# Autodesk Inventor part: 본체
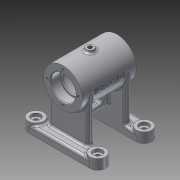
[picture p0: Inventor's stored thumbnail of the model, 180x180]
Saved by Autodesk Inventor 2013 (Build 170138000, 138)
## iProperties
Created: 2015-11
Part Number: 본체
Material: 알루미늄 6061
Document SubType Name: Modeling
Designer: cad10
Density: 2.40731 g/cm^3
Mass: 318.269 g
Surface Area: 455.809 cm^2
Volume: 132.209 cm^3
Author: cad10
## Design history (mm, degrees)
sketch "스케치1"
  geometry: L1 (-40, -20)-(40, -20); L2 (50, -30)-(50, -30); L3 (40, -40)-(-40, -40); L4 (-50, -30)-(-50, -30); L5 (-40, 40)-(40, 40); L6 (50, 30)-(50, 30); L7 (40, 20)-(-40, 20); L8 (-50, 30)-(-50, 30); A1 r 10 centre (-40, 30) between (-40, 40) and (-50, 30); A2 r 10 centre (-40, 30) between (-50, 30) and (-40, 20); A3 r 10 centre (40, 30) between (40, 20) and (50, 30); A4 r 10 centre (40, 30) between (50, 30) and (40, 40); A5 r 10 centre (40, -30) between (50, -30) and (40, -20); A6 r 10 centre (40, -30) between (40, -40) and (50, -30); A7 r 10 centre (-40, -30) between (-50, -30) and (-40, -40); A8 r 10 centre (-40, -30) between (-40, -20) and (-50, -30); 3 further points
  constraints: 16 end point, 16 point on circle, 16 tangent, 8 centre point, 7 equal radius, 4 parallel, 2 horizontal, 2 midpoint, 2 perpendicular, 2 vertical alignment
  dimensions: "d0" = 100 distance between parallel lines of L8 L6; "d2" = 20 distance between parallel lines of L5 L7; "d3" = 20 distance between parallel lines of L3 L1; "d4" = 100 distance between parallel lines of L4 L2; "d5" = 80 distance between parallel lines of L5 L3; "d6" = 40 distance from line of L5 point (0, 0); "d7" = 10 radius of A1
extrude "돌출1" new body sketch "스케치1" distance "d8" = 10; taper "d9" = 0 deg
sketch "스케치2"
  geometry: C1 r 10 at (-40, -30); A1 r 10 centre (40, -30) between (40, -40) and (40, -20) reference; A2 r 10 centre (-40, -30) between (-40, -20) and (-40, -40) reference; 2 further points
  constraints: 2 coincident, 1 centre point, 1 concentric, 1 vertical alignment, 2 other
extrude "돌출2" join sketch "스케치2" distance "d10" = 3; taper "d11" = 0 deg
sketch "스케치3"
  geometry: A1 r 10 centre (-40, 30) between (-40, 40) and (-40, 20) reference; A2 r 10 centre (40, 30) between (40, 20) and (40, 40) reference; 3 further points
  constraints: 2 coincident, 2 vertical alignment, 4 other
extrude "돌출3" join sketch "스케치3" distance "d12" = 3; taper "d13" = 0 deg
node "작업 평면2"
sketch "스케치5"
  geometry: L1 (-40, 0)-(40, 0) reference; C1 r 25 at (0, 68); 2 further points
  constraints: 1 centre point, 1 midpoint, 1 vertical alignment
  dimensions: "d16" = 50 diameter of C1; "d18" = 68 distance from line of C1.centre L1
extrude "돌출4" join sketch "스케치5" stored distance "d19" = 70; taper "d20" = 0 deg
node "작업 평면3"
sketch "스케치6"
  geometry: L1 (-35, 93)-(-35, 43) reference; L2 (35, 43)-(35, 93) reference; L3 (-35, 84)-(-23, 84); L4 (-23, 84)-(-23, 82); L5 (-23, 82)-(-21, 82); L6 (-21, 82)-(-21, 89); L7 (-21, 89)-(21, 89); L8 (21, 89)-(21, 82); L9 (21, 82)-(23, 82); L10 (23, 82)-(23, 84); L11 (23, 84)-(35, 84); L12 (-35, 68)-(35, 68); 1 further point
  constraints: 20 end point, 6 parallel, 3 perpendicular, 2 midpoint, 2 point on line
  dimensions: "d22" = 32 diameter of L3 L12; "d24" = 28 diameter of L5 L12; "d25" = 42 diameter of L7 L12; "d26" = 28 diameter of L9 L12; "d27" = 32 diameter of L11 L12; "d28" = 12 distance between parallel lines of L2 L10; "d29" = 12 distance between parallel lines of L1 L4; "d30" = 42 distance between parallel lines of L8 L6; "d31" = 2 distance between parallel lines of L4 L6
revolve "회전1" sketch "스케치6" stored, may be unused: angle "d32" = 90 deg
sketch "스케치7"
  geometry: L1 (40, -20)-(-40, -20) reference; L2 (-25, -20)-(25, -20); L3 (25, -20)-(25, -28); L4 (25, -28)-(-25, -28); L5 (-25, -28)-(-25, -20); 3 further points
  constraints: 8 end point, 2 midpoint, 2 parallel, 2 vertical alignment, 1 horizontal, 1 perpendicular, 1 point on line
  dimensions: "d33" = 50 distance between parallel lines of L3 L5; "d35" = 8 distance between parallel lines of L1 L4
extrude "돌출5" join sketch "스케치7" stored distance "d38" = 0; taper "d39" = 0 deg
sketch "스케치8"
  geometry: L1 (-40, 20)-(40, 20) reference; L2 (-25, 20)-(25, 20); L3 (25, 20)-(25, 28); L4 (25, 28)-(-25, 28); L5 (-25, 28)-(-25, 20); 3 further points
  constraints: 8 end point, 2 midpoint, 2 parallel, 2 vertical alignment, 1 horizontal, 1 perpendicular, 1 point on line
  dimensions: "d40" = 8 distance between parallel lines of L4 L2; "d42" = 50 distance between parallel lines of L5 L3
extrude "돌출6" join sketch "스케치8" stored distance "d43" = 70; taper "d44" = 0 deg
node "작업 평면4"
sketch "스케치9"
  geometry: C1 r 5 at (0, 0); 1 further point
  constraints: 1 centre point, 1 coincident
  dimensions: "d46" = 10 diameter of C1
extrude "돌출7" join sketch "스케치9" stored distance "d48" = 70; taper "d49" = 0 deg
sketch "스케치10"
  geometry: C1 r 16 at (0, 0) reference; 2 further points
  constraints: 1 vertical alignment
  dimensions: "d50" = 20 distance of point (0, 20) C1.centre
hole "구멍1" sketch "스케치10" at (0, 20) diameter "d51" = 3.242; stored, may be unused: countersink angle "d55" = 90 deg, drill point angle "d57" = 118 deg; dims "d52" = 8, "d53" = 4, "d54" = 2, "d56" = 10
sketch "스케치11"
  geometry: C1 r 10 at (0, 0) reference; 2 further points
  constraints: 1 coincident
hole "구멍2" sketch "스케치11" at (0, 0) diameter "d61" = 6; stored, may be unused: countersink angle "d65" = 90 deg, drill point angle "d67" = 118 deg; dims "d62" = 6, "d63" = 12, "d64" = 4, "d66" = 13
sketch "스케치12"
  geometry: C1 r 5 at (0, 0) reference; 1 further point
  constraints: 1 coincident
hole "구멍3" sketch "스케치12" at (0, 0) diameter "d68" = 5.188; stored, may be unused: countersink angle "d72" = 90 deg, drill point angle "d74" = 118 deg; dims "d69" = 6, "d70" = 12, "d71" = 4, "d73" = 13
node "작업 평면5"
sketch "스케치13"
  geometry: L1 (40, 20)-(-40, 20) reference; L2 (40, -20)-(-40, -20) reference; L3 (-4, 20)-(4, 20); L4 (4, 20)-(4, -20); L5 (4, -20)-(-4, -20); L6 (-4, -20)-(-4, 20); 2 further points
  constraints: 8 end point, 2 parallel, 2 point on line, 1 horizontal, 1 midpoint, 1 perpendicular, 1 vertical alignment
  dimensions: "d76" = 8 distance between parallel lines of L4 L6
extrude "돌출8" join sketch "스케치13" stored distance "d78" = 70; taper "d79" = 0 deg
sketch "스케치14" dims "d82" = 23
  geometry: L1 (6.5, 28)-(6.5, 12); L2 (13.5, 12)-(13.5, 28); A1 r 3.5 centre (10, 28) between (13.5, 28) and (10, 31.5); A2 r 3.5 centre (10, 28) between (10, 31.5) and (6.5, 28); A3 r 3.5 centre (10, 12) between (6.5, 12) and (10, 8.5); A4 r 3.5 centre (10, 12) between (10, 8.5) and (13.5, 12); 2 further points; 2 other entities
  constraints: 8 point on circle, 4 centre point, 4 end point, 4 tangent, 3 equal radius, 2 coincident, 1 horizontal alignment, 1 midpoint, 1 parallel, 1 vertical, 8 other
  dimensions: "d80" = 7 distance between parallel lines of L1 L2; "d83" = 3.5 radius of A1; "d84" = 33 horizontal distance of A1.centre point (-23, 20)
extrude "돌출9" cut sketch "스케치14" stored distance "d85" = 10; taper "d86" = 0 deg
node "작업 평면9"
  node "작업 평면8"
sketch "스케치16"
  geometry: L1 (-35, 93)-(-35, 43) reference; L2 (35, 93)-(-35, 93) reference; 2 further points
  constraints: 1 other
  dimensions: "d91" = 35 distance from line of L1 point (0, 68); "d92" = 25 distance from line of L2 point (0, 68)
feature "엠보싱1" sketch "스케치16" dims "d0" = 100, "d2" = 20, "d3" = 20, "d4" = 100, "d5" = 80, "d6" = 40, "d7" = 10, "d93" = 0.5, "d94" = 0
node "작업 평면10"
fillet "모깎기1" dims "d96" = 3
fillet "모깎기2" dims "d97" = 3
fillet "모깎기3" dims "d98" = 3
fillet "모깎기4" dims "d99" = 3
node "작업 평면15"
  node "작업 평면14"
sketch "스케치19"
  geometry: C1 r 6 at (0, 3.89); 1 further point
  constraints: 1 centre point, 1 vertical alignment
  dimensions: "d108" = 12 diameter of C1; "d110" = 55 distance of point (0, 58.89) C1.centre
extrude "돌출10" join sketch "스케치19" stored distance "d111" = 10; taper "d112" = 0 deg
sketch "스케치20"
  geometry: C1 r 6 at (0, 0) reference; 2 further points
  constraints: 1 coincident
hole "구멍4" sketch "스케치20" at (0, 0) diameter "d113" = 5.188; stored, may be unused: countersink angle "d117" = 90 deg, drill point angle "d119" = 0 deg; dims "d114" = 6, "d115" = 4, "d116" = 2, "d118" = 8
fillet "모깎기5" dims "d120" = 3
chamfer "모따기1" distance "d121" = 1; stored, may be unused: second distance "d122" = 2, angle "d123" = 45 deg
fillet "모깎기6" dims "d124" = 3
fillet "모깎기7" dims "d125" = 0.3
node "작업축3"
node "솔리드1"
pattern_circular "원형 패턴1" dims angle "d59" = 360 deg
mirror "대칭1"
mirror "대칭2"
mirror "대칭3"
node "작업축2"
other parameters: "d15" = 90 deg, "d21" = 90 deg, "d45" = 96, "d75" = 23, "d89" = 90 deg, "d90" = 25.5, "d95" = 90 deg, "d106" = 30 deg, "d107" = -28
